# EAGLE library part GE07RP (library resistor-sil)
SIL RESISTOR
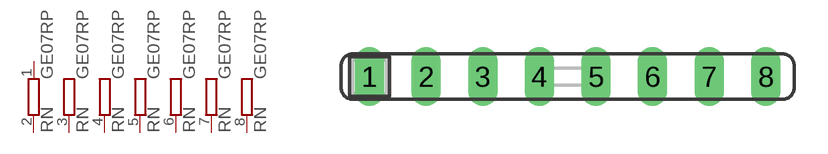
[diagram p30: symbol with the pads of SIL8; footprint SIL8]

Designator prefix RN; gates A=R-PV B=R-PV1 C=R-PV1 D=R-PV1 E=R-PV1 F=R-PV1 G=R-PV1

## GE07RP (OC_FARNELL: unknown; OC_NEWARK: unknown)  [SIL8]
1  A:1  pas
2  A:2  pas
3  B:2  pas
4  C:2  pas
5  D:2  pas
6  E:2  pas
7  F:2  pas
8  G:2  pas

## Footprint SIL8 (pad centres in mm)
Single In Line
drill 0.813 long: 1 -8.89,0; 2 -6.35,0; 3 -3.81,0; 4 -1.27,0; 5 1.27,0; 6 3.81,0; 7 6.35,0; 8 8.89,0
